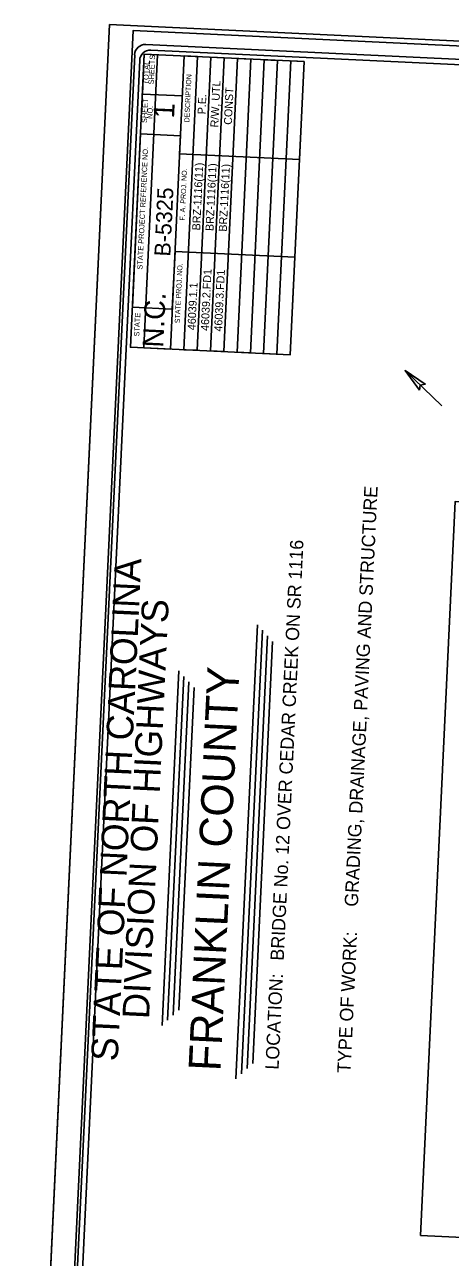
# Model space of a CAD drawing. Extents: x 2166609 to 2169084, y 841593 to 845234.
# Drawn here: x 2166609 to 2167447, y 842808 to 845234 of the extents above; entities that cross this region are included whole.
import ezdxf

# ---------------------------------------------------------------- set-up
doc = ezdxf.new("R2010")
doc.units = 0
for name, color, linetype in [('Default', 7, 'Continuous'), ('Sheet Cutting Line CELL', 7, 'Continuous'), ('Sheet Data Field CELL', 7, 'Continuous'), ('Sheet Plan CELL', 7, 'Continuous'), ('Sheet Plot Border Inside CELL', 7, 'Continuous'), ('Sheet Plot Border Outside CELL', 7, 'Continuous'), ('Sheet Title CELL', 7, 'Continuous'), ('Sheet Title Data Points CELL', 7, 'Continuous'), ('Typical Terminator CELL', 7, 'Continuous')]:
    doc.layers.add(name, color=color, linetype=linetype)

# ---------------------------------------------------------------- blocks, each defined once
blk = doc.blocks.new('TERMINATOR')
at = {"layer": 'Typical Terminator CELL'}
blk.add_lwpolyline([(-0.469, 0.081), (0, 0), (-0.471, -0.083), (-0.411, 0)], close=True, dxfattribs=at)

msp = doc.modelspace()

# ---------------------------------------------------------------- linework, layer by layer
at = {"layer": 'Default'}
msp.add_line((2167430.4, 844484.1), (2167358.2, 844553.2), dxfattribs=at)
at = {"layer": 'Sheet Cutting Line CELL'}
msp.add_line((2166609.4, 841701.7), (2166776.2, 845234.2), dxfattribs=at)
at = {"layer": 'Sheet Plan CELL'}
msp.add_lwpolyline([(2167388.5, 842851), (2167456.7, 844295.5), (2168336.9, 844253.9), (2168268.7, 842809.4)], close=True, dxfattribs=at)
at = {"layer": 'Sheet Plot Border Inside CELL'}
msp.add_lwpolyline([(2168871, 841622.3), (2169036.1, 845118), (2166822.9, 845222.5), (2166657.8, 841726.8)], close=True, dxfattribs=at)
at = {"layer": 'Sheet Plot Border Outside CELL'}
msp.add_lwpolyline([(2166776.2, 845234.2), (2166609.4, 841701.7), (2168916.8, 841592.8), (2169083.6, 845125.2)], close=True, dxfattribs=at)
at = {"layer": 'Sheet Title CELL'}
for p, q in [((2167025.4, 843159.5), (2167067.6, 844053.1)), ((2167036.4, 843169.5), (2167077.6, 844042.1)), ((2167047.4, 843179.5), (2167087.6, 844031.2)), ((2167058.4, 843189.5), (2167097.6, 844020.2)), ((2166879.9, 843264.5), (2166912.8, 843962.5)), ((2166890.8, 843274.5), (2166922.8, 843951.5)), ((2166901.8, 843284.5), (2166932.8, 843940.5)), ((2166912.8, 843294.4), (2166942.8, 843929.5))]:
    msp.add_line(p, q, dxfattribs=at)
for points in [[(2166826, 845175.1), (2166679.3, 842070.5)], [(2167132.3, 844584.6), (2167159.6, 845161.4), (2167133.4, 845162.7), (2167106.1, 844585.8), (2167079.9, 844587.1), (2167107.2, 845163.9), (2167081, 845165.2), (2167053.7, 844588.3), (2167027.5, 844589.5), (2167054.7, 845166.4), (2167028.5, 845167.6), (2167001.2, 844590.8), (2166975, 844592), (2167002.3, 845168.9), (2166976.1, 845170.1), (2166948.8, 844593.3), (2166922.6, 844594.5), (2166949.9, 845171.3), (2166923.6, 845172.6), (2166896.4, 844595.7), (2166843.9, 844598.2), (2166871.2, 845175.1), (2166844.9, 845176.3), (2166817.7, 844599.4), (2167132.3, 844584.6), (2167141.5, 844776.8), (2166905.5, 844788), (2166900.1, 844674.4), (2166821.4, 844678.1), (2166837.5, 845019), (2166916.2, 845015.3), (2166914.5, 844980.2), (2167150.5, 844969.1), (2167159.6, 845161.4), (2166844.9, 845176.3), (2166841.2, 845097.6), (2166919.9, 845094)], [(2169008.5, 845093), (2166848, 845195.1)], [(2168609.5, 845101.4), (2166857.9, 845184.1)], [(2166836, 845164.1), (2166695.3, 842185.5)]]:
    msp.add_lwpolyline(points, dxfattribs=at)
for centre in [(2166846.8, 845174.1), (2166856.8, 845163.1)]:
    msp.add_arc(centre, 21, 87.2959, 177.2959, dxfattribs=at)
at = {"layer": 'Sheet Title Data Points CELL'}
for p, q in [((2167141.3, 843857.5), (2167141.3, 843857.5)), ((2167015.4, 843611), (2167015.4, 843611))]:
    msp.add_line(p, q, dxfattribs=at)

# ---------------------------------------------------------------- block references
at = {"layer": 'Default', "xscale": 99.99999999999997, "yscale": 99.99999999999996, "rotation": 136.269790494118}
msp.add_blockref('TERMINATOR', (2167358.2, 844553.2), dxfattribs=at)

# ---------------------------------------------------------------- texts
at = {"layer": 'Sheet Data Field CELL'}
for s, height, p in [('R/W, UTL', 15.75, (2166990.6, 845031.6)), ('CONST', 15.75, (2167017.2, 845036.8)), ('P.E.', 15.75, (2166965.4, 845057.5)), ('BRZ-1116(11)', 15.75, (2166954.8, 844829)), ('BRZ-1116(11)', 15.75, (2166981, 844827.8)), ('BRZ-1116(11)', 15.75, (2167007.2, 844826.5)), ('B-5325', 31.5, (2166896.1, 844777.4)), ('46039.2.FD1', 15.75, (2166971.7, 844631.2)), ('46039.3.FD1', 15.75, (2166997.9, 844629.9)), ('46039.1.1', 15.75, (2166945.5, 844632.7)), ('GRADING, DRAINAGE, PAVING AND STRUCTURE', 26.25, (2167265.3, 843497.7)), ('BRIDGE No. 12 OVER CEDAR CREEK ON SR 1116', 26.25, (2167119.3, 843391.5)), ('FRANKLIN COUNTY', 63, (2166994.8, 843173.7))]:
    msp.add_text(s, height=height, rotation=87.2959, dxfattribs=at).set_placement(p)
at = {"layer": 'Sheet Title CELL'}
for s, height, p in [('SHEETS', 10.5, (2166863.5, 845116.5)), ('TOTAL', 10.5, (2166852.9, 845116.3)), ('DESCRIPTION', 10.08, (2166933.5, 845041.5)), ('SHEET', 10.5, (2166850.1, 845040.4)), ('1', 40.6, (2166903.4, 845049.2)), ('NO.', 10.5, (2166860.9, 845048.6)), ('STATE PROJECT REFERENCE NO.', 10.5, (2166841.2, 844752)), ('F. A. PROJ. NO.', 10.08, (2166924.4, 844848.3)), ('STATE PROJ. NO.', 10.08, (2166914.8, 844646.3)), ('N.C.', 40.63, (2166882.1, 844598)), ('STATE', 10.5, (2166835, 844620.2)), ('STATE OF NORTH CAROLINA', 52.5, (2166792.5, 843193.3)), ('DIVISION OF HIGHWAYS', 52.5, (2166854.2, 843276.4)), ('TYPE OF WORK:', 26.25, (2167250.8, 843170.3)), ('LOCATION: ', 26.25, (2167109.2, 843177))]:
    msp.add_text(s, height=height, rotation=87.2959, dxfattribs=at).set_placement(p)

doc.saveas('drawing.dxf')
